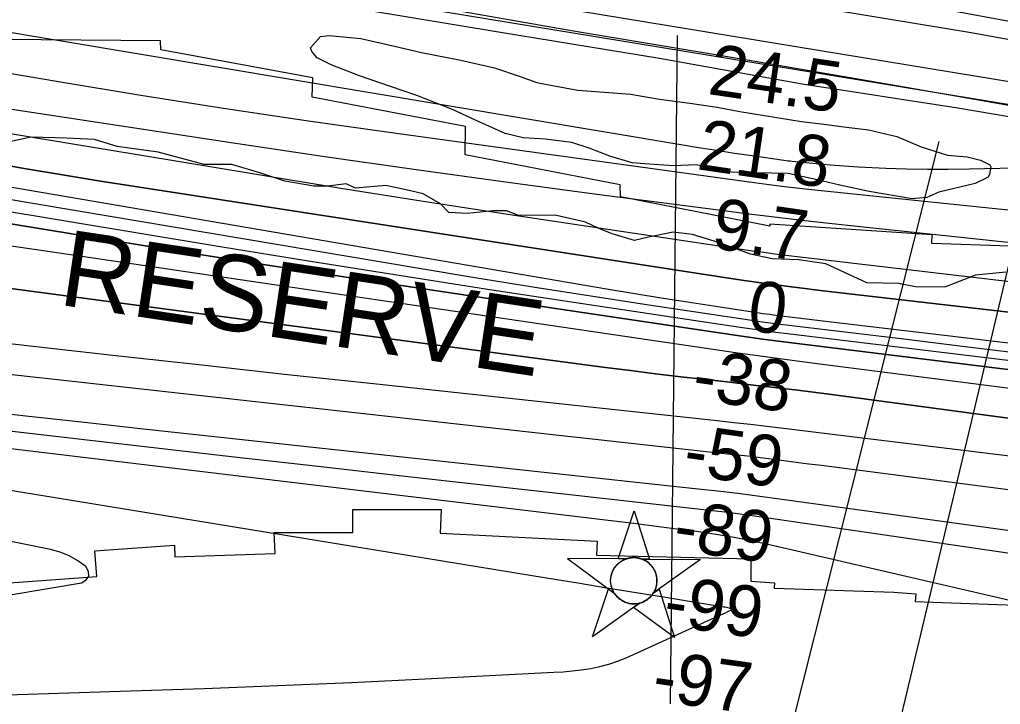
# Model space of a CAD drawing. Extents: x 3508733 to 3546731, y 546897 to 572481.
# Drawn here: x 3524852 to 3526144, y 565153 to 566055 of the extents above; entities that cross this region are included whole.
import ezdxf

# ---------------------------------------------------------------- set-up
doc = ezdxf.new("R2010")
doc.units = 0
for name, color, linetype in [('V-CHAN-NAID', 7, 'Continuous'), ('V-FLOD-BASE', 7, 'Continuous'), ('V-LEVE-TOET', 7, 'Continuous'), ('V-RIVR-EDGE', 7, 'Continuous'), ('V-RIVR-RANG', 7, 'Continuous'), ('V-RRAP-RVMT', 7, 'Continuous'), ('V-RRAP-RVMT-IDEN', 7, 'Continuous'), ('V-SITE-VEGE', 7, 'Continuous'), ('V-SURV-LINE', 7, 'Continuous'), ('V-TOPO-DPTH', 7, 'Continuous'), ('V-TOPO-MAJR', 7, 'Continuous'), ('V-TOPO-MINR', 7, 'Continuous'), ('V-TOPO-SHOR', 7, 'Continuous'), ('V-TOPO-WATR', 7, 'Continuous'), ('V-UTIL-LINE', 7, 'Continuous')]:
    doc.layers.add(name, color=color, linetype=linetype)

msp = doc.modelspace()

# ---------------------------------------------------------------- linework, layer by layer
at = {"layer": 'V-CHAN-NAID'}
for points in [[(3525650.1, 565344.4), (3525640.5, 565344.4), (3525661.6, 565407.9), (3525681.8, 565344.1), (3525672.2, 565344.2), (3525670.7, 565344.8), (3525668.6, 565345.4), (3525666.5, 565345.9), (3525664.5, 565346.2), (3525663.3, 565346.3), (3525661.8, 565346.4), (3525660.1, 565346.4), (3525658.7, 565346.3), (3525656.8, 565346.1), (3525655.4, 565345.9), (3525653.6, 565345.5), (3525652.1, 565345.1), (3525651.1, 565344.7)], [(3525650.1, 565344.4), (3525573.6, 565344.9), (3525635.1, 565299.5), (3525634, 565301.4), (3525633.2, 565303.1), (3525632.4, 565305), (3525631.7, 565307.1), (3525631.3, 565308.4), (3525631, 565310), (3525630.7, 565311.5), (3525630.5, 565313.1), (3525630.4, 565314.8), (3525630.4, 565316.4), (3525630.5, 565318.5), (3525630.7, 565320.1), (3525631.1, 565322.3), (3525631.6, 565324.2), (3525632.2, 565326.1), (3525632.8, 565327.8), (3525633.6, 565329.4), (3525634.4, 565330.9), (3525635.4, 565332.6), (3525636.5, 565334.1), (3525637.5, 565335.4), (3525638.5, 565336.5), (3525639.8, 565337.9), (3525640.8, 565338.8), (3525642.5, 565340.2), (3525643.7, 565341.1), (3525645.4, 565342.2), (3525647.2, 565343.1), (3525648.6, 565343.8)], [(3525672.2, 565344.2), (3525748.7, 565343.7), (3525686.5, 565299.2), (3525687.4, 565300.6), (3525688.4, 565302.5), (3525689.1, 565304.1), (3525689.9, 565306), (3525690.4, 565307.8), (3525690.8, 565309.5), (3525691.2, 565311.5), (3525691.3, 565313), (3525691.5, 565315.2), (3525691.4, 565317.3), (3525691.3, 565319.5), (3525691, 565321.3), (3525690.5, 565323.5), (3525689.9, 565325.7), (3525689.1, 565327.6), (3525688.5, 565329.1), (3525687.5, 565331), (3525686.4, 565332.7), (3525685.2, 565334.4), (3525683.9, 565336), (3525682.6, 565337.3), (3525681, 565338.9), (3525679.3, 565340.3), (3525677.6, 565341.4), (3525675.7, 565342.6), (3525674.2, 565343.3)], [(3525668.5, 565286.2), (3525606.3, 565241.7), (3525627.4, 565305.2), (3525635.1, 565299.5), (3525635.8, 565298.6), (3525637.1, 565296.7), (3525638.4, 565295.3), (3525639.8, 565293.8), (3525641.2, 565292.5), (3525642.7, 565291.4), (3525644.1, 565290.4), (3525645.7, 565289.3), (3525647.5, 565288.4), (3525649.3, 565287.6), (3525650.7, 565287.1), (3525652.3, 565286.5), (3525654.6, 565286), (3525656.1, 565285.7), (3525658.1, 565285.4), (3525659.6, 565285.3), (3525661.5, 565285.3), (3525663.2, 565285.4), (3525664.9, 565285.6), (3525666.8, 565285.9)], [(3525686.5, 565299.2), (3525694.3, 565304.7), (3525714.5, 565241), (3525660.7, 565280.7), (3525668.5, 565286.2), (3525670.2, 565286.7), (3525671.8, 565287.3), (3525673.9, 565288.2), (3525675.7, 565289.1), (3525677.5, 565290.2), (3525679.3, 565291.4), (3525680.8, 565292.7), (3525682.1, 565293.8), (3525683.5, 565295.2), (3525684.7, 565296.6), (3525685.8, 565298.1)]]:
    msp.add_lwpolyline(points, close=True, dxfattribs=at)
msp.add_circle((3525660.9, 565315.8), 30.5, dxfattribs=at)
at = {"layer": 'V-FLOD-BASE'}
msp.add_lwpolyline([(3527002.6, 565995.7), (3526928.9, 566006.7), (3526890.6, 566009.2), (3526863.9, 566009.4), (3526827.7, 566007.1), (3526794.8, 566000.6), (3526742.7, 565989.5), (3526684.4, 565970.3), (3526606.1, 565938.2), (3526534.1, 565910.9), (3526495.6, 565894.9), (3526466.9, 565891.1), (3526442.9, 565890), (3526394.5, 565901.4), (3526294.9, 565918.8), (3526170, 565939.2), (3526009.6, 565966.9), (3525802.8, 566002.5), (3525581.7, 566039.6), (3525390.6, 566073), (3525179.7, 566107.9), (3524998.1, 566135.1), (3524872.1, 566156.4)], dxfattribs=at)
at = {"layer": 'V-LEVE-TOET'}
for points in [[(3525065.2, 566203.2), (3525253.6, 566174.6), (3525416.1, 566150.4), (3525646.1, 566111.1), (3525859.8, 566078.2), (3526102.7, 566038.1), (3526328.6, 565997.6), (3526390.1, 565989.4), (3526435.9, 565988.9), (3526487.9, 565995.9), (3526511.2, 566001.2), (3526586, 566023.6), (3526725.9, 566073.5), (3526776.7, 566087.3), (3526828.7, 566095), (3526897.8, 566101.1)], [(3525304.9, 566068.2), (3525485.1, 566038.4), (3525694.7, 566004.1), (3525883, 565970), (3526087.8, 565938.6), (3526250.9, 565910.9)]]:
    msp.add_lwpolyline(points, dxfattribs=at)
at = {"layer": 'V-RIVR-EDGE'}
msp.add_lwpolyline([(3526151.3, 565722.2), (3526111.4, 565718.1), (3526071.6, 565702.8), (3526034.2, 565702.3), (3526009.7, 565707.3), (3525968, 565708), (3525914.2, 565733.2), (3525878.6, 565738.2), (3525843.1, 565739.5), (3525814.9, 565745.7), (3525773.9, 565760.6), (3525738.4, 565771.7), (3525712.7, 565774.8), (3525680.2, 565768.1), (3525661.8, 565763.9), (3525632.4, 565772.5), (3525614.1, 565779.9), (3525597.5, 565787.9), (3525558.9, 565796.6), (3525508.1, 565797.4), (3525493.4, 565802.9), (3525475, 565803), (3525441.9, 565799.4), (3525417.4, 565800.6), (3525406.4, 565812.3), (3525383.2, 565825.2), (3525364.8, 565829.6), (3525334.2, 565836.4), (3525294.3, 565832.8), (3525282.1, 565838.4), (3525257.6, 565835.4), (3525239.2, 565835.4), (3525201.2, 565842.2), (3525169.4, 565852.7), (3525131.4, 565863.9), (3525094.7, 565863.9), (3525034, 565880), (3524980.1, 565887.5), (3524950.1, 565896.8), (3524913.4, 565898.7), (3524866.8, 565900), (3524830, 565892.2)], dxfattribs=at)
at = {"layer": 'V-RIVR-RANG'}
msp.add_line((3525718.2, 566033.6), (3525709, 565153.7), dxfattribs=at)
at = {"layer": 'V-RRAP-RVMT'}
for points in [[(3526258.3, 565752.8), (3526053.8, 565759.9), (3526054, 565771.3), (3525840.3, 565785.2), (3525840.4, 565782.7), (3525643.5, 565821.3), (3525642.9, 565837.2), (3525438.8, 565876.6), (3525439.3, 565914.1), (3525237.3, 565952.4), (3525238.2, 565977.9), (3525037.5, 566014.9), (3525037.3, 566027), (3524827.9, 566028.5)], [(3524813.6, 565311.3), (3524953.5, 565321.4), (3524950.8, 565355.1), (3525055.7, 565362.5), (3525056.3, 565347.1), (3525188.3, 565351.7), (3525187.2, 565379.4), (3525290.8, 565379.5), (3525290.6, 565409.4), (3525407.3, 565409.4), (3525406, 565378.5), (3525612.7, 565367.7), (3525611.6, 565349.4), (3525815.1, 565344.7), (3525815, 565315.3), (3525846.2, 565312.9), (3525846, 565306.1), (3526003.7, 565300.6), (3526032.4, 565298.4), (3526031.9, 565288.5), (3526235.9, 565280.9)]]:
    msp.add_lwpolyline(points, dxfattribs=at)
at = {"layer": 'V-SITE-VEGE'}
msp.add_lwpolyline([(3525674.9, 565864.7), (3525658.6, 565866.3), (3525629.2, 565874.8), (3525602, 565885.3), (3525579.5, 565893), (3525544, 565897.5), (3525515.3, 565899.2), (3525491.4, 565904.9), (3525453.3, 565921.7), (3525422, 565936.3), (3525375, 565954.6), (3525340.3, 565966.6), (3525299.4, 565980.7), (3525262, 565995.4), (3525243.6, 566004.5), (3525236.8, 566012.8), (3525234.8, 566017.6), (3525248, 566032.5), (3525259.6, 566033.7), (3525301.3, 566029.9), (3525320.4, 566025.6), (3525345.6, 566019.8), (3525381.1, 566011.3), (3525432.9, 566001.2), (3525477.3, 565991.2), (3525511.4, 565979.9), (3525533.2, 565972.1), (3525553.6, 565967.8), (3525587.1, 565962), (3525628, 565958.9), (3525656.7, 565956.5), (3525695, 565950), (3525734.6, 565944.8), (3525770.7, 565939.6), (3525800.8, 565933.9), (3525849.2, 565925.8), (3525882, 565920.7), (3525911.4, 565917), (3525941.4, 565913.3), (3525970.1, 565909.6), (3526007.6, 565901), (3526039.6, 565887), (3526074.3, 565876.4), (3526100.3, 565874.1), (3526118, 565869.8), (3526130.3, 565863.5), (3526131.6, 565860.8), (3526129.5, 565851.2), (3526128, 565847.1), (3526110.9, 565839.1), (3526062.9, 565827.3), (3526047.1, 565820.6), (3526027.9, 565818.7), (3525971.3, 565828.2), (3525932.4, 565836.8), (3525902.4, 565843.9), (3525864.2, 565851.9), (3525820.5, 565853), (3525789.7, 565854), (3525743.3, 565863.3), (3525713.2, 565862.3)], close=True, dxfattribs=at)
at = {"layer": 'V-SURV-LINE'}
for points in [[(3524549.8, 566236.9), (3526455.7, 565924)], [(3526450.9, 565894.3), (3524545, 566207.3)]]:
    msp.add_lwpolyline(points, dxfattribs=at)
at = {"layer": 'V-TOPO-DPTH'}
for points in [[(3524090.1, 566008.2), (3524232.7, 565980.7), (3524375.2, 565952.6), (3524592.4, 565909.2), (3524631.5, 565901.4), (3524670.6, 565893.8), (3524709.7, 565886.2), (3524748.8, 565878.7), (3524765.4, 565875.5), (3524812.9, 565866.7), (3524860.4, 565858.2), (3524908, 565850.3), (3524955.7, 565842.6), (3525771.7, 565716.3), (3525806.4, 565711.2), (3525841, 565706.3), (3525875.8, 565701.8), (3525910.6, 565697.6), (3526934.8, 565580.1)], [(3524090.1, 566008.2), (3524232.7, 565980.7), (3524375.2, 565952.6), (3524592.4, 565909.2), (3524631.5, 565901.4), (3524670.6, 565893.8), (3524709.7, 565886.2), (3524748.8, 565878.7), (3524765.4, 565875.5), (3524812.9, 565866.7), (3524860.4, 565858.2), (3524908, 565850.3), (3524955.7, 565842.6), (3525771.7, 565716.3), (3525806.4, 565711.2), (3525841, 565706.3), (3525875.8, 565701.8), (3525910.6, 565697.6), (3526934.8, 565580.1)], [(3526199.5, 565611.7), (3526108.1, 565622.7), (3526016.7, 565633.7), (3525854.1, 565653.3), (3525844, 565654.6), (3525833.8, 565655.9), (3525823.7, 565657.3), (3525813.6, 565658.8), (3525680.8, 565678.7), (3525604.4, 565690.4), (3525527.9, 565702.3), (3525451.6, 565714.7), (3525375.3, 565727.3), (3524691, 565842.3), (3524677.7, 565844.5), (3524664.5, 565846.8), (3524651.2, 565849.1), (3524638, 565851.4), (3524544.6, 565867.7), (3524484.7, 565878.3), (3524424.9, 565889.1), (3524365.1, 565900.3), (3524305.3, 565911.7), (3524073.4, 565956.4)], [(3526199.5, 565611.7), (3526108.1, 565622.7), (3526016.7, 565633.7), (3525854.1, 565653.3), (3525844, 565654.6), (3525833.8, 565655.9), (3525823.7, 565657.3), (3525813.6, 565658.8), (3525680.8, 565678.7), (3525604.4, 565690.4), (3525527.9, 565702.3), (3525451.6, 565714.7), (3525375.3, 565727.3), (3524691, 565842.3), (3524677.7, 565844.5), (3524664.5, 565846.8), (3524651.2, 565849.1), (3524638, 565851.4), (3524544.6, 565867.7), (3524484.7, 565878.3), (3524424.9, 565889.1), (3524365.1, 565900.3), (3524305.3, 565911.7), (3524073.4, 565956.4)], [(3526986.4, 565672.9), (3525934.8, 565784.4), (3525894.2, 565788.8), (3525853.5, 565793.5), (3525812.9, 565798.4), (3525772.4, 565803.6), (3525612.3, 565824.5), (3525491.7, 565840.6), (3525371.2, 565857.3), (3525250.8, 565874.6), (3525130.5, 565892.5), (3524690.7, 565959.3)], [(3523965.3, 565933.5), (3524104.2, 565909.3), (3524243.2, 565885.4), (3524382.2, 565861.8), (3524602.2, 565824.7), (3524631.3, 565819.8), (3524660.4, 565815), (3524689.5, 565810.2), (3524718.6, 565805.4), (3524918, 565772.9), (3525046.9, 565752.2), (3525175.8, 565731.9), (3525304.8, 565712.1), (3525433.9, 565692.7), (3525788.5, 565640.1), (3525809.6, 565637), (3525830.7, 565634.1), (3525851.8, 565631.3), (3525872.9, 565628.6), (3526418, 565561.4)], [(3523965.3, 565933.5), (3524104.2, 565909.3), (3524243.2, 565885.4), (3524382.2, 565861.8), (3524602.2, 565824.7), (3524631.3, 565819.8), (3524660.4, 565815), (3524689.5, 565810.2), (3524718.6, 565805.4), (3524918, 565772.9), (3525046.9, 565752.2), (3525175.8, 565731.9), (3525304.8, 565712.1), (3525433.9, 565692.7), (3525788.5, 565640.1), (3525809.6, 565637), (3525830.7, 565634.1), (3525851.8, 565631.3), (3525872.9, 565628.6), (3526418, 565561.4)], [(3526777.2, 565489.4), (3525892.5, 565602.7), (3525860, 565607), (3525827.5, 565611.4), (3525795, 565615.9), (3525762.5, 565620.6), (3524873.8, 565751.4), (3524837.6, 565756.8), (3524801.3, 565762.3), (3524765.1, 565767.9), (3524728.9, 565773.5), (3524692.7, 565779.2), (3524656.5, 565785), (3524620.3, 565790.7), (3524584.1, 565796.5), (3523856.5, 565912.8)], [(3526777.2, 565489.4), (3525892.5, 565602.7), (3525860, 565607), (3525827.5, 565611.4), (3525795, 565615.9), (3525762.5, 565620.6), (3524873.8, 565751.4), (3524837.6, 565756.8), (3524801.3, 565762.3), (3524765.1, 565767.9), (3524728.9, 565773.5), (3524692.7, 565779.2), (3524656.5, 565785), (3524620.3, 565790.7), (3524584.1, 565796.5), (3523856.5, 565912.8)], [(3524061.9, 565823), (3524179.4, 565803.7), (3524296.8, 565784.4), (3524414.2, 565765), (3524601, 565734), (3524625, 565730.2), (3524649, 565726.5), (3524673, 565723), (3524697.1, 565719.7), (3525623.5, 565596.8), (3525656.6, 565592.5), (3525689.6, 565588.4), (3525722.7, 565584.4), (3525755.8, 565580.6), (3525787.7, 565577.1), (3525804.8, 565575.1), (3525822, 565573.1), (3525839.1, 565571.1), (3525856.3, 565569.1), (3525873.4, 565567), (3525890.6, 565564.8), (3525907.7, 565562.6), (3525924.8, 565560.4), (3527000.1, 565416.8)], [(3524061.9, 565823), (3524179.4, 565803.7), (3524296.8, 565784.4), (3524414.2, 565765), (3524601, 565734), (3524625, 565730.2), (3524649, 565726.5), (3524673, 565723), (3524697.1, 565719.7), (3525623.5, 565596.8), (3525656.6, 565592.5), (3525689.6, 565588.4), (3525722.7, 565584.4), (3525755.8, 565580.6), (3525787.7, 565577.1), (3525804.8, 565575.1), (3525822, 565573.1), (3525839.1, 565571.1), (3525856.3, 565569.1), (3525873.4, 565567), (3525890.6, 565564.8), (3525907.7, 565562.6), (3525924.8, 565560.4), (3527000.1, 565416.8)]]:
    msp.add_lwpolyline(points, dxfattribs=at)
at = {"layer": 'V-TOPO-MAJR'}
for points in [[(3526752.2, 565406.9), (3525858.3, 565516.2), (3525836.4, 565518.9), (3525814.6, 565521.4), (3525792.7, 565523.9), (3525770.8, 565526.3), (3525317.9, 565574.9), (3525204.8, 565587.1), (3525091.6, 565599.5), (3524978.5, 565612.1), (3524865.4, 565624.8), (3524663.9, 565647.6), (3524651.5, 565649.1), (3524639.2, 565650.7), (3524626.9, 565652.5), (3524614.7, 565654.3), (3524512, 565670.7), (3524448.4, 565681.1), (3524384.9, 565691.8), (3524321.5, 565702.9), (3524258.1, 565714.3), (3523785.6, 565800.9)], [(3525790.1, 565278.1), (3525790, 565278.4), (3525789.7, 565278.7), (3525789, 565278.9), (3525787.6, 565279.4), (3525786.9, 565279.5), (3525781, 565280.8), (3525779.2, 565281.1), (3525702.9, 565293.5), (3525664.2, 565299.8), (3525625.6, 565306.1), (3525587, 565312.5), (3525548.4, 565318.8), (3524621.5, 565470.3)], [(3524807.8, 565164.7), (3524997.8, 565170.7), (3525094.9, 565174), (3525191.9, 565177.7), (3525289, 565181.9), (3525386, 565186.6), (3525555.4, 565195.2), (3525567.7, 565196), (3525579.9, 565197.1), (3525592.1, 565198.6), (3525604.3, 565200.4), (3525616.3, 565202.8), (3525628.1, 565205.8), (3525639.6, 565209.8), (3525651, 565214.4), (3525772.7, 565269.5), (3525775.8, 565270.9), (3525778.9, 565272.3), (3525781.9, 565273.7), (3525784.9, 565275.2), (3525789.7, 565277.5), (3525790, 565277.8), (3525790.1, 565278.1)]]:
    msp.add_lwpolyline(points, dxfattribs=at)
at = {"layer": 'V-TOPO-MINR'}
for points in [[(3526216.7, 565702.4), (3526093.4, 565717), (3525876.1, 565742.2), (3525861.4, 565744), (3525846.7, 565745.9), (3525832.1, 565747.9), (3525817.4, 565750), (3525617.9, 565779.5), (3525503.6, 565796.8), (3525389.3, 565814.3), (3525275.1, 565832.5), (3525161, 565851), (3524716.6, 565924.4), (3524696, 565927.8), (3524675.4, 565931.3), (3524654.8, 565934.9), (3524634.2, 565938.6), (3524498, 565963.2), (3524409.4, 565979.2), (3524320.7, 565995.2), (3524232.1, 566011.2), (3524143.4, 566027.2), (3523550, 566134.5)], [(3526269.8, 565792.1), (3526133, 565806.1), (3525899.4, 565830.1), (3525879.4, 565832.2), (3525859.4, 565834.5), (3525839.5, 565837), (3525819.5, 565839.7), (3525338.4, 565905.9), (3525229.3, 565921.5), (3525120.3, 565937.7), (3525011.5, 565954.9), (3524902.8, 565972.7), (3524747.4, 565999), (3524716.4, 566004.3), (3524685.5, 566009.8), (3524654.6, 566015.5), (3524623.8, 566021.4), (3524445.2, 566056)], [(3526265.4, 565861.3), (3526102.8, 565857.8), (3526075.3, 565857.4), (3526047.8, 565857.4), (3526020.4, 565857.9), (3525992.9, 565858.8), (3525974.9, 565859.5), (3525956.4, 565860.5), (3525938, 565861.6), (3525919.5, 565863.1), (3525901.1, 565864.8), (3525869.8, 565867.9), (3525867.1, 565868.2), (3525864.3, 565868.5), (3525861.5, 565868.9), (3525858.8, 565869.3), (3525817.1, 565875.2), (3525793.5, 565878.6), (3525770, 565882.2), (3525746.4, 565885.9), (3525722.9, 565889.8), (3524701.7, 566060.7)], [(3526199.5, 565611.7), (3526108.1, 565622.7), (3526016.7, 565633.7), (3525854.1, 565653.3), (3525844, 565654.6), (3525833.8, 565655.9), (3525823.7, 565657.3), (3525813.6, 565658.8), (3525680.8, 565678.7), (3525604.4, 565690.4), (3525527.9, 565702.3), (3525451.6, 565714.7), (3525375.3, 565727.3), (3524691, 565842.3), (3524677.7, 565844.5), (3524664.5, 565846.8), (3524651.2, 565849.1), (3524638, 565851.4), (3524544.6, 565867.7), (3524484.7, 565878.3), (3524424.9, 565889.1), (3524365.1, 565900.3), (3524305.3, 565911.7), (3524073.4, 565956.4)], [(3526986.4, 565672.9), (3525934.8, 565784.4), (3525894.2, 565788.8), (3525853.5, 565793.5), (3525812.9, 565798.4), (3525772.4, 565803.6), (3525612.3, 565824.5), (3525491.7, 565840.6), (3525371.2, 565857.3), (3525250.8, 565874.6), (3525130.5, 565892.5), (3524690.7, 565959.3)], [(3526418, 565561.4), (3525872.9, 565628.6), (3525851.8, 565631.3), (3525830.7, 565634.1), (3525809.6, 565637), (3525788.5, 565640.1), (3525433.9, 565692.7), (3525304.8, 565712.1), (3525175.8, 565731.9), (3525046.9, 565752.2), (3524918, 565772.9), (3524718.6, 565805.4), (3524689.5, 565810.2), (3524660.4, 565815), (3524631.3, 565819.8), (3524602.2, 565824.7), (3524382.2, 565861.8), (3524243.2, 565885.4), (3524104.2, 565909.3), (3523965.3, 565933.5)], [(3526265.5, 565592), (3526121.1, 565609.6), (3525863.5, 565641), (3525847.9, 565642.9), (3525832.3, 565645), (3525816.7, 565647.2), (3525801.1, 565649.4), (3525593.2, 565680.4), (3525473.8, 565698.6), (3525354.4, 565717.1), (3525235.1, 565736.1), (3525115.8, 565755.6), (3524705, 565823.6), (3524683.7, 565827.1), (3524662.4, 565830.7), (3524641.1, 565834.3), (3524619.9, 565837.9), (3524466.5, 565864.4), (3524368.6, 565881.5), (3524270.8, 565899), (3524173, 565916.8), (3524075.3, 565935)], [(3526777.2, 565489.4), (3525892.5, 565602.7), (3525860, 565607), (3525827.5, 565611.4), (3525795, 565615.9), (3525762.5, 565620.6), (3524873.8, 565751.4), (3524837.6, 565756.8), (3524801.3, 565762.3), (3524765.1, 565767.9), (3524728.9, 565773.5), (3524692.7, 565779.2), (3524656.5, 565785), (3524620.3, 565790.7), (3524584.1, 565796.5), (3523856.5, 565912.8)], [(3527008, 565525.9), (3526081.4, 565637.3), (3526040.4, 565642.2), (3525999.4, 565647.1), (3525958.4, 565652), (3525917.4, 565656.9), (3525844.7, 565665.6), (3525840, 565666.2), (3525835.4, 565666.8), (3525830.7, 565667.4), (3525826.1, 565668.1), (3525766.1, 565677.2), (3525731.5, 565682.5), (3525696.9, 565688), (3525662.3, 565693.6), (3525627.7, 565699.4), (3524676.6, 565861.6)], [(3527000.1, 565416.8), (3525924.8, 565560.4), (3525907.7, 565562.6), (3525890.6, 565564.8), (3525873.4, 565567), (3525856.3, 565569.1), (3525839.1, 565571.1), (3525822, 565573.1), (3525804.8, 565575.1), (3525787.7, 565577.1), (3525755.8, 565580.6), (3525722.7, 565584.4), (3525689.6, 565588.4), (3525656.6, 565592.5), (3525623.5, 565596.8), (3524697.1, 565719.7), (3524673, 565723), (3524649, 565726.5), (3524625, 565730.2), (3524601, 565734), (3524414.2, 565765), (3524296.8, 565784.4), (3524179.4, 565803.7), (3524061.9, 565823)], [(3526994.3, 565326), (3525908.3, 565467.4), (3525891.7, 565469.5), (3525875.1, 565471.6), (3525858.5, 565473.7), (3525841.8, 565475.8), (3525810.6, 565479.8), (3525806.6, 565480.2), (3525792.4, 565481.7), (3525784.4, 565482.6), (3525776.3, 565483.5), (3525768.2, 565484.3), (3525760.1, 565485.2), (3524699.2, 565602.8), (3524666.6, 565606.6), (3524634.1, 565610.8), (3524601.6, 565615.5), (3524569.2, 565620.6), (3524229.2, 565676), (3524107.1, 565695.9), (3523985, 565715.6)], [(3527023.7, 565262.5), (3525853, 565423.4), (3525827.2, 565426.8), (3525801.5, 565430), (3525775.7, 565433.1), (3525749.9, 565436), (3525092.3, 565507.1), (3525014.8, 565515.5), (3524937.3, 565524.1), (3524859.8, 565532.7), (3524782.3, 565541.4), (3524644.4, 565557), (3524635.9, 565558), (3524627.4, 565559.1), (3524618.9, 565560.2), (3524610.5, 565561.5), (3524534.1, 565573.2), (3524487.4, 565580.6), (3524440.8, 565588.2), (3524394.3, 565596.1), (3524347.8, 565604.3), (3524035.5, 565660.7)], [(3526174.6, 565349), (3526049, 565367.6), (3525822.9, 565400.5), (3525810.3, 565402.3), (3525797.7, 565404), (3525785.1, 565405.5), (3525772.5, 565407), (3525576.6, 565428.7), (3525466, 565441), (3525355.5, 565453.4), (3525245, 565466), (3525134.4, 565478.6), (3524663.2, 565532.9), (3524643.9, 565535.3), (3524624.7, 565537.7), (3524605.4, 565540.4), (3524586.2, 565543.3), (3524412.8, 565569.9), (3524306.9, 565585.8), (3524200.9, 565601.1), (3524094.8, 565615.7)], [(3526277.8, 565261.6), (3525845.5, 565361.9), (3525819.4, 565367.5), (3525793.2, 565372.7), (3525766.9, 565377), (3525740.5, 565380.9), (3525714, 565384.3), (3525687.5, 565387.7), (3525661, 565391), (3525634.5, 565394.2), (3524682.2, 565508.3), (3524652, 565512.1), (3524621.9, 565516), (3524591.7, 565520.3), (3524561.6, 565524.8), (3524196.3, 565581), (3524078.5, 565598.7)], [(3524681.4, 565271.3), (3524689.5, 565272.3), (3524697.6, 565273.6), (3524933.2, 565313), (3524939.4, 565317.1), (3524942.9, 565321.9), (3524942.3, 565327.8), (3524938.9, 565334.4), (3524928.3, 565342), (3524917, 565348.5), (3524904.9, 565353.2), (3524892.3, 565356.7), (3524644.8, 565406.8), (3524626.8, 565410.4), (3524608.7, 565413.9), (3524590.6, 565417.5), (3524572.5, 565420.9), (3524362.4, 565460.8), (3524239.1, 565483.4), (3524115.6, 565504.8), (3523991.8, 565524.5)]]:
    msp.add_lwpolyline(points, dxfattribs=at)
at = {"layer": 'V-TOPO-SHOR'}
msp.add_lwpolyline([(3526688.3, 566112.1), (3526573.7, 566068.8), (3526474.3, 566039.1), (3526426.3, 566030), (3526374.3, 566025.1), (3526324.4, 566024.9), (3526274.6, 566032.9), (3526181.7, 566047.5), (3526043.9, 566072.9), (3525865.7, 566100.7), (3525738.8, 566120.4), (3525662.3, 566134.9)], dxfattribs=at)
at = {"layer": 'V-TOPO-WATR'}
msp.add_lwpolyline([(3526934.8, 565580.1), (3525910.6, 565697.6), (3525875.8, 565701.8), (3525841, 565706.3), (3525806.4, 565711.2), (3525771.7, 565716.3), (3524955.7, 565842.6), (3524908, 565850.3), (3524860.4, 565858.2), (3524812.9, 565866.7), (3524765.4, 565875.5), (3524748.8, 565878.7), (3524709.7, 565886.2), (3524670.6, 565893.8), (3524631.5, 565901.4), (3524592.4, 565909.2), (3524375.2, 565952.6), (3524232.7, 565980.7), (3524090.1, 566008.2)], dxfattribs=at)
at = {"layer": 'V-UTIL-LINE'}
for points in [[(3525407, 563288.4), (3526063.3, 565894.4)], [(3526187.4, 565867.5), (3525566.5, 563265.6)]]:
    msp.add_lwpolyline(points, dxfattribs=at)

# ---------------------------------------------------------------- texts
at = {"layer": 'V-RIVR-RANG'}
for s, rotation, p in [('24.5', 351.7083, (3525757, 565956.9)), ('21.8', 351.7083, (3525742.8, 565857.9)), ('9.7', 351.7083, (3525761.5, 565754.2)), ('0', 351.9879, (3525808.5, 565646.1)), ('-38', 351.9879, (3525736.1, 565555.3)), ('-59', 351.9879, (3525724.3, 565456)), ('-89', 351.9879, (3525711.1, 565356.9)), ('-99', 351.9879, (3525698, 565257.7)), ('-97', 351.9879, (3525683.3, 565158.8))]:
    msp.add_text(s, height=67, rotation=rotation, dxfattribs=at).set_placement(p)
at = {"layer": 'V-RRAP-RVMT-IDEN'}
msp.add_text('RESERVE', height=100, rotation=351.4499, dxfattribs=at).set_placement((3524901.2, 565679.6))

doc.saveas('drawing.dxf')
